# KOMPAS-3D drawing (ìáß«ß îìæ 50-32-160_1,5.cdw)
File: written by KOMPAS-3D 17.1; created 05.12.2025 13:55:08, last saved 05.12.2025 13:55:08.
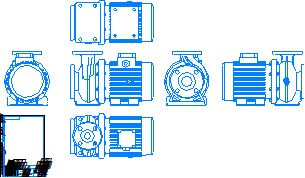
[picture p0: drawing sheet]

Sheet 1: A4, portrait

Title block, sheet 1: name: Насос МНС / 50-32-160_1,1; material: Сталь 10  ГОСТ 1050-88; mass: 75,61; sheets: 1; sheet format: A4

Views: Проекционный вид 2, Проекционный вид 3, Проекционный вид 4, Проекционный вид 5, Проекционный вид 6
Referenced files in \\adlc.lan\data\АДЛ_ПКД\3D-модели\ADL production\Насосы ГРАНПАМП\Насосы ГРАНПАМП серии МНС\KOMPAS 3D\: Насос МНС 50-32-160_1,5.m3d
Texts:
  Andrey
  АДЛ
Dimensions and other numbers on the sheet: 1:1; 1; 50-32-160_1,1; 75,61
